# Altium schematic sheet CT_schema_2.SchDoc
size 287 x 169 mm
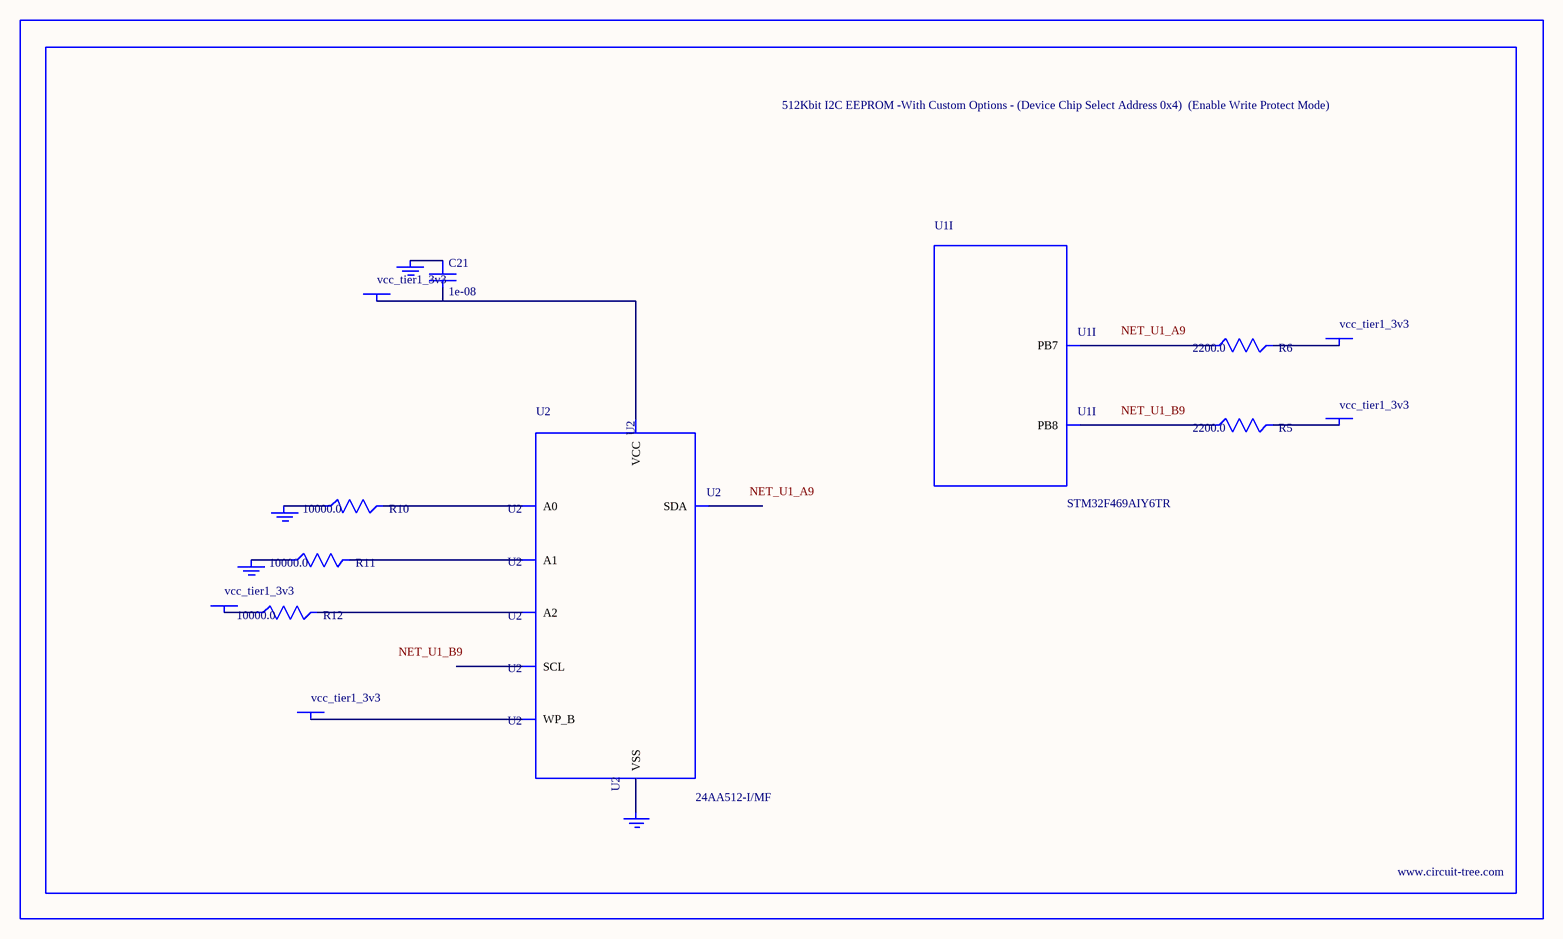
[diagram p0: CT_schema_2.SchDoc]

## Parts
BORDER1  (no value)
C21  1e-08  [C0402]
GND_INSTANCE_1_0  (no value)
GND_INSTANCE_1_1  (no value)
GND_INSTANCE_1_2  (no value)
GND_INSTANCE_1_3  (no value)
POWER_INSTANCE_1_0  vcc_tier1_3v3
POWER_INSTANCE_1_1  vcc_tier1_3v3
POWER_INSTANCE_1_2  vcc_tier1_3v3
POWER_INSTANCE_1_3  vcc_tier1_3v3
POWER_INSTANCE_1_4  vcc_tier1_3v3
R5  2200.0  [R0603]
R6  2200.0  [R0603]
R10  10000.0  [R0603]
R11  10000.0  [R0603]
R12  10000.0  [R0603]
U1  STM32F469AIY6TR  [WLCSP168]  (part I of 14)
U2  24AA512-I/MF  [DFN8-S]

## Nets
NetC21_1: C21.1 GND_INSTANCE_1_2.0(GND)
NetC21_2: C21.2 POWER_INSTANCE_1_2.0(PWR) U2.8(VCC)
NetGND_INSTANCE_1_0_0: GND_INSTANCE_1_0.0(GND) R10.1
NetGND_INSTANCE_1_1_0: GND_INSTANCE_1_1.0(GND) R11.1
NetGND_INSTANCE_1_3_0: GND_INSTANCE_1_3.0(GND) U2.4(VSS)
NetPOWER_INSTANCE_1_0_0: POWER_INSTANCE_1_0.0(PWR) R12.1
NetPOWER_INSTANCE_1_1_0: POWER_INSTANCE_1_1.0(PWR) U2.7(WP_B)
NetPOWER_INSTANCE_1_3_0: POWER_INSTANCE_1_3.0(PWR) R6.2
NetPOWER_INSTANCE_1_4_0: POWER_INSTANCE_1_4.0(PWR) R5.2
NetR5_1: R5.1 U1.B9(PB8)
NetR6_1: R6.1 U1.A9(PB7)
NetR10_2: R10.2 U2.1(A0)
NetR11_2: R11.2 U2.2(A1)
NetR12_2: R12.2 U2.3(A2)

Not connected (* = marked no-connect by the designer): U2 5(SDA) 6(SCL)

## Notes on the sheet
- Labels drawn without touching a wire or pin: NET_U1_A9, NET_U1_B9

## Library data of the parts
BORDER1 = BORDER_PAGE1
C21 = C0402C103K3RAC
GND_INSTANCE_1_0-GND_INSTANCE_1_3 = GND
POWER_INSTANCE_1_0-POWER_INSTANCE_1_4 = PWR
R5 R6 = RC0603JR-072K2L
R10-R12 = RC0603JR-0710KL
